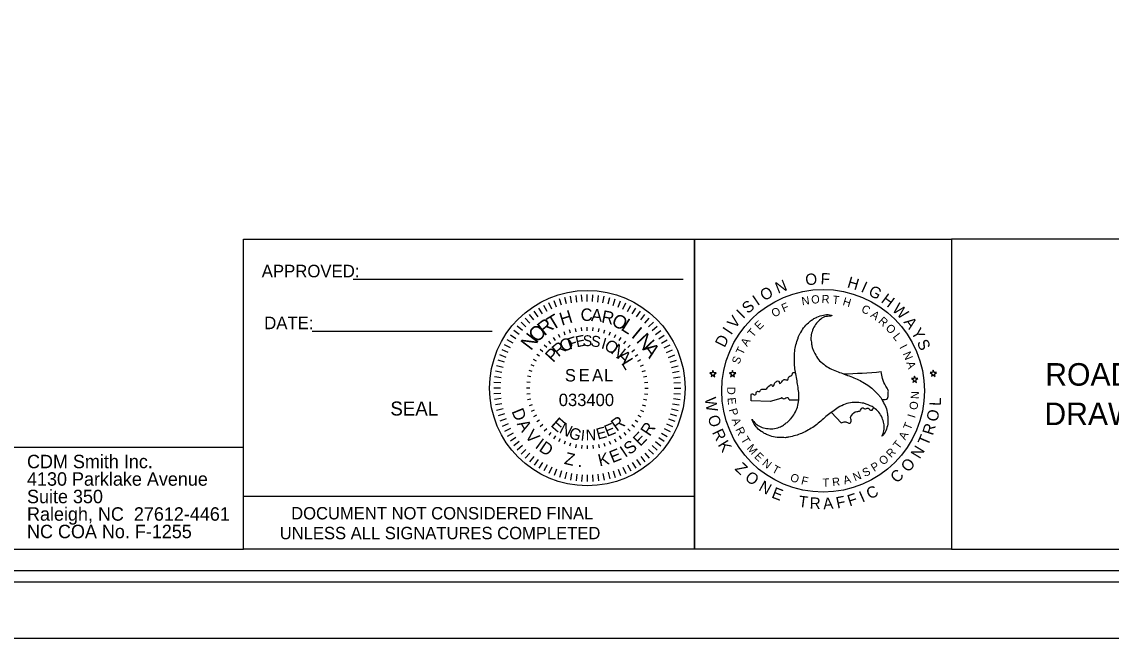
# Model space of a CAD drawing. Extents: x 0 to 1868, y 0 to 1100.
# Drawn here: x 1004.4 to 1487.6, y 0 to 273.5 of the extents above; entities that cross this region are included whole.
import ezdxf

# ---------------------------------------------------------------- set-up
doc = ezdxf.new("R2010")
doc.units = 0
for name, color, linetype in [('Exist Utilities Gas Test Hole SUE LOS A CELL', 7, 'Continuous'), ('Exist Utilities Sanitary Sewer Test Hole SUE LOS A CELL', 7, 'Continuous'), ('P_RDY_ROW_Permanent_Easement_CELL', 7, 'Continuous'), ('Sheet Block Title CELL', 7, 'Continuous'), ('Sheet_Cross_Section_Scale_CELL', 7, 'Continuous'), ('Sheet_Plan', 7, 'Continuous'), ('Sheet_Symbology_CELL', 7, 'Continuous')]:
    doc.layers.add(name, color=color, linetype=linetype)

msp = doc.modelspace()

# ---------------------------------------------------------------- linework, layer by layer
at = {"layer": 'Exist Utilities Gas Test Hole SUE LOS A CELL'}
for p, q in [((1309.58, 117.72), (1310.46, 117.07)), ((1310.66, 117.72), (1309.58, 117.72)), ((1310.46, 117.07), (1310.14, 116.03)), ((1310.14, 116.03), (1310.98, 116.67)), ((1310.98, 118.72), (1310.66, 117.72)), ((1311.34, 117.72), (1310.98, 118.72)), ((1310.98, 116.67), (1311.87, 116.03)), ((1310.98, 116.67), (1311.86, 116.03)), ((1312.43, 117.72), (1311.34, 117.72)), ((1311.54, 117.07), (1312.43, 117.72)), ((1311.54, 117.07), (1312.43, 117.72)), ((1311.87, 116.03), (1311.54, 117.07)), ((1311.86, 116.03), (1311.54, 117.07)), ((1319.34, 117.7), (1318.25, 117.7)), ((1318.25, 117.7), (1319.14, 117.06)), ((1319.14, 117.06), (1318.82, 116.02)), ((1318.82, 116.02), (1319.66, 116.66)), ((1319.66, 118.71), (1319.34, 117.7)), ((1320.02, 117.7), (1319.66, 118.71)), ((1319.66, 116.66), (1320.54, 116.02)), ((1321.1, 117.7), (1320.02, 117.7)), ((1320.22, 117.06), (1321.1, 117.7)), ((1320.54, 116.02), (1320.22, 117.06)), ((1400.43, 116.22), (1400.11, 115.21)), ((1400.79, 115.21), (1400.43, 116.22)), ((1408.38, 117.86), (1407.3, 117.86)), ((1407.3, 117.86), (1408.18, 117.21)), ((1408.18, 117.21), (1407.86, 116.17)), ((1407.86, 116.17), (1408.7, 116.81)), ((1408.7, 118.86), (1408.38, 117.86)), ((1409.07, 117.86), (1408.7, 118.86)), ((1408.7, 116.81), (1409.59, 116.17)), ((1410.15, 117.86), (1409.07, 117.86)), ((1409.27, 117.21), (1410.15, 117.86)), ((1409.59, 116.17), (1409.27, 117.21)), ((1400.11, 115.21), (1399.02, 115.21)), ((1399.02, 115.21), (1399.9, 114.57)), ((1399.9, 114.57), (1399.58, 113.53)), ((1399.58, 113.53), (1400.43, 114.17)), ((1400.43, 114.17), (1401.31, 113.53)), ((1401.87, 115.21), (1400.79, 115.21)), ((1400.99, 114.57), (1401.87, 115.21)), ((1401.31, 113.53), (1400.99, 114.57)), ((1327.9, 105.27), (1327.99, 107.93)), ((1341.1, 106.37), (1336.29, 104.96)), ((1336.29, 104.96), (1327.9, 105.27)), ((1344.8, 105.81), (1349.01, 105.77)), ((1363.55, 100.19), (1367.86, 95.52))]:
    msp.add_line(p, q, dxfattribs=at)
for start, end in [(265.6785, 265.9762), (271.2035, 275.3236)]:
    msp.add_arc((1363.94, 350.45), 233.19, start, end, dxfattribs=at)
for points in [[(1328.31, 97.16), (1330.06, 95.15), (1332.23, 93.75), (1334.73, 93.11), (1337.55, 92.94), (1340.42, 93.62), (1342.33, 94.58), (1343.13, 95.23), (1344.53, 96.33), (1345.52, 97.4), (1347.18, 99.76), (1348.47, 102.56), (1349.01, 105.75), (1349.04, 106.02), (1349.01, 109.02), (1348.61, 112.06), (1348.18, 114.98), (1347.64, 118.02), (1347.16, 121.02), (1347.1, 123.95), (1347.29, 127.31), (1347.78, 130.18), (1348.72, 133.13), (1349.23, 134.53), (1349.92, 135.66), (1351.67, 138.31), (1353.95, 140.46), (1355.45, 141.59), (1356.88, 142.34), (1357.12, 142.47), (1359.96, 143.38), (1362.75, 143.49), (1363.7, 143.25)], [(1363.77, 143.33), (1363.7, 143.25), (1361.12, 142.77), (1358.78, 141.56), (1356.98, 139.74), (1355.45, 137.4), (1354.6, 134.55), (1354.46, 132.43), (1354.65, 131.41), (1354.89, 129.64), (1355.29, 128.25), (1356.56, 125.64), (1358.3, 123.12), (1360.82, 121.05), (1361.04, 120.89), (1363.61, 119.41), (1366.49, 118.23), (1369.22, 117.16), (1372.1, 116.11), (1374.94, 114.98), (1377.52, 113.59), (1380.34, 111.76), (1382.56, 109.91), (1384.66, 107.63), (1385.63, 106.47), (1386.24, 105.3), (1387.69, 102.47), (1388.39, 99.41), (1388.63, 97.54), (1388.58, 95.92), (1388.58, 95.66), (1387.91, 92.73), (1386.59, 90.26), (1385.95, 89.59)], [(1327.99, 107.93), (1327.9, 108.18), (1328.35, 108.46), (1329.6, 107.95), (1330.22, 108.49), (1330.19, 109.03), (1330.7, 109.57), (1331.55, 109.4), (1332.31, 110.36), (1333.02, 110.56), (1334.51, 110.56), (1336.29, 112.33), (1337.03, 112.45), (1337.23, 111.97), (1337.68, 111.88), (1338.47, 113.35), (1338.67, 113.55), (1340.02, 114.11), (1340.39, 113.83), (1340.5, 113.18), (1340.7, 113.07), (1341.15, 113.38), (1341.78, 114.17), (1342.91, 114.77), (1344.21, 114.6), (1344.43, 115.67), (1345.96, 116.69), (1346.27, 117.31), (1346.35, 117.93)], [(1385.88, 106.04), (1388.34, 106.35), (1388.71, 108.3), (1388.74, 109.93), (1387.72, 111.83), (1386.2, 115.3), (1385.57, 118.27)], [(1344.8, 105.81), (1344.46, 106.46), (1343.78, 106.66), (1342.85, 106.18), (1342.17, 106.2), (1341.41, 106.77), (1341.1, 106.37)], [(1385.95, 89.59), (1386.81, 92.06), (1386.94, 94.66), (1386.24, 97.16), (1384.98, 99.65), (1382.97, 101.8), (1381.2, 102.98), (1380.2, 103.34), (1378.59, 104.03), (1377.12, 104.35), (1374.27, 104.59), (1371.18, 104.33), (1368.15, 103.17), (1367.91, 103.07), (1365.33, 101.54), (1362.89, 99.68), (1360.55, 97.86), (1358.22, 95.87), (1355.83, 93.94), (1353.33, 92.43), (1350.33, 90.9), (1347.61, 89.91), (1344.61, 89.24), (1343.1, 88.97), (1341.79, 89.03), (1338.65, 89.19), (1335.62, 90.1), (1333.9, 90.83), (1332.53, 91.71), (1332.29, 91.84), (1330.09, 93.86), (1328.61, 96.22), (1328.31, 97.16)], [(1367.86, 95.52), (1369.55, 96.03), (1370.96, 95.49), (1371.64, 95.38), (1372.21, 95.8), (1372.04, 97.93), (1372.52, 98.91), (1374.81, 100.61), (1376.22, 100.92), (1377.27, 102.22), (1377.69, 102.19), (1378.34, 101.82), (1379.78, 102.11), (1380.94, 101.17), (1381.62, 101.23), (1382.16, 102.29)]]:
    msp.add_spline(points, degree=3, dxfattribs=at)
at = {"layer": 'Exist Utilities Sanitary Sewer Test Hole SUE LOS A CELL'}
msp.add_lwpolyline([(0, 0), (1688, 0), (1688, 1100), (0, 1100)], close=True, dxfattribs=at)
at = {"layer": 'P_RDY_ROW_Permanent_Easement_CELL'}
for p, q in [((1151.36, 159.37), (1297.7, 159.37)), ((1302.85, 153.55), (1302.85, 39.55)), ((1133.24, 136.3), (1213.03, 136.3)), ((740.76, 30), (1652.71, 30)), ((173.28, 25), (1652.71, 25))]:
    msp.add_line(p, q, dxfattribs=at)
for points in [[(1102.81, 177.05), (1302.85, 177.05), (1302.85, 39.55), (1102.81, 39.55)], [(1302.85, 177.05), (1416.85, 177.05), (1416.85, 39.55), (1302.85, 39.55)], [(1652.85, 177.05), (1416.85, 177.05), (1416.85, 39.55), (1652.85, 39.55)]]:
    msp.add_lwpolyline(points, close=True, dxfattribs=at)
msp.add_circle((1255.25, 110.96), 43.34, dxfattribs=at)
at = {"layer": 'Sheet Block Title CELL'}
msp.add_lwpolyline([(907.1, 39.55), (1102.81, 39.55), (1102.81, 84.55), (907.1, 84.55)], close=True, dxfattribs=at)
at = {"layer": 'Sheet_Cross_Section_Scale_CELL'}
msp.add_circle((1359.85, 109.76), 44.97, dxfattribs=at)
at = {"layer": 'Sheet_Plan'}
for p, q in [((1243.8, 147.7), (1242.91, 150.56)), ((1246.04, 148.32), (1245.32, 151.23)), ((1248.31, 148.81), (1247.77, 151.76)), ((1250.61, 149.16), (1250.25, 152.13)), ((1252.92, 149.37), (1252.74, 152.36)), ((1255.25, 149.44), (1255.25, 152.44)), ((1257.57, 149.37), (1257.75, 152.36)), ((1259.89, 149.16), (1260.25, 152.13)), ((1262.18, 148.81), (1262.73, 151.76)), ((1264.46, 148.32), (1265.17, 151.23)), ((1266.69, 147.69), (1267.59, 150.56)), ((1233.39, 142.63), (1231.69, 145.09)), ((1235.34, 143.89), (1233.79, 146.46)), ((1237.37, 145.03), (1235.97, 147.68)), ((1239.46, 146.05), (1238.23, 148.78)), ((1241.6, 146.94), (1240.54, 149.74)), ((1268.89, 146.94), (1269.96, 149.74)), ((1271.04, 146.05), (1272.27, 148.78)), ((1273.13, 145.03), (1274.52, 147.68)), ((1275.15, 143.89), (1276.7, 146.46)), ((1277.1, 142.63), (1278.81, 145.09)), ((1228.04, 138.17), (1225.92, 140.29)), ((1229.73, 139.76), (1227.74, 142.01)), ((1231.52, 141.25), (1229.67, 143.61)), ((1278.98, 141.25), (1280.83, 143.61)), ((1280.76, 139.76), (1282.75, 142.01)), ((1282.46, 138.17), (1284.57, 140.29)), ((1224.96, 134.69), (1222.6, 136.54)), ((1226.45, 136.47), (1224.2, 138.46)), ((1245.5, 134.5), (1244.92, 135.89)), ((1247.85, 135.35), (1247.41, 136.78)), ((1250.28, 135.96), (1249.98, 137.43)), ((1252.75, 136.32), (1252.6, 137.81)), ((1255.25, 136.45), (1255.25, 137.94)), ((1257.75, 136.32), (1257.89, 137.81)), ((1260.22, 135.96), (1260.51, 137.43)), ((1262.64, 135.35), (1263.08, 136.78)), ((1265, 134.5), (1265.58, 135.89)), ((1284.05, 136.47), (1286.29, 138.46)), ((1285.54, 134.69), (1287.9, 136.54)), ((1222.32, 130.87), (1219.75, 132.42)), ((1223.58, 132.82), (1221.12, 134.52)), ((1239.08, 130.66), (1238.13, 131.82)), ((1241.09, 132.15), (1240.26, 133.4)), ((1243.23, 133.44), (1242.53, 134.76)), ((1267.26, 133.44), (1267.97, 134.76)), ((1269.41, 132.15), (1270.24, 133.4)), ((1271.42, 130.66), (1272.37, 131.82)), ((1286.92, 132.82), (1289.38, 134.52)), ((1288.18, 130.87), (1290.74, 132.42)), ((1219.27, 124.6), (1216.47, 125.67)), ((1220.16, 126.75), (1217.43, 127.98)), ((1221.18, 128.84), (1218.52, 130.23)), ((1234.06, 125.12), (1232.81, 125.95)), ((1235.55, 127.13), (1234.39, 128.08)), ((1237.23, 128.98), (1236.17, 130.04)), ((1273.27, 128.98), (1274.33, 130.04)), ((1274.95, 127.13), (1276.11, 128.08)), ((1276.44, 125.12), (1277.69, 125.95)), ((1289.32, 128.84), (1291.97, 130.24)), ((1290.34, 126.75), (1293.07, 127.98)), ((1291.22, 124.6), (1294.03, 125.67)), ((1217.89, 120.17), (1214.98, 120.89)), ((1218.51, 122.41), (1215.65, 123.3)), ((1231.7, 120.71), (1230.32, 121.28)), ((1232.77, 122.97), (1231.45, 123.68)), ((1277.72, 122.97), (1279.05, 123.68)), ((1278.79, 120.71), (1280.18, 121.28)), ((1291.99, 122.41), (1294.84, 123.3)), ((1292.61, 120.17), (1295.52, 120.89)), ((1217.4, 117.9), (1214.45, 118.44)), ((1230.25, 115.93), (1228.78, 116.22)), ((1230.86, 118.36), (1229.42, 118.79)), ((1279.63, 118.36), (1281.07, 118.79)), ((1280.24, 115.93), (1281.71, 116.22)), ((1293.1, 117.9), (1296.05, 118.44)), ((1216.84, 113.28), (1213.85, 113.46)), ((1217.05, 115.6), (1214.08, 115.96)), ((1229.89, 113.46), (1228.39, 113.61)), ((1280.61, 113.46), (1282.1, 113.61)), ((1293.44, 115.6), (1296.42, 115.96)), ((1293.66, 113.28), (1296.65, 113.46)), ((1216.77, 110.96), (1213.77, 110.96)), ((1216.84, 108.64), (1213.85, 108.46)), ((1217.05, 106.32), (1214.08, 105.96)), ((1229.76, 110.96), (1228.26, 110.96)), ((1229.89, 108.46), (1228.39, 108.32)), ((1280.61, 108.46), (1282.1, 108.32)), ((1280.73, 110.96), (1282.23, 110.96)), ((1293.44, 106.32), (1296.42, 105.96)), ((1293.66, 108.64), (1296.65, 108.46)), ((1293.73, 110.96), (1296.72, 110.96)), ((1217.4, 104.02), (1214.45, 103.48)), ((1217.89, 101.75), (1214.98, 101.03)), ((1230.25, 105.99), (1228.78, 105.7)), ((1230.86, 103.56), (1229.42, 103.13)), ((1279.63, 103.56), (1281.07, 103.13)), ((1280.24, 105.99), (1281.71, 105.7)), ((1292.61, 101.75), (1295.52, 101.03)), ((1293.1, 104.02), (1296.05, 103.48)), ((1218.51, 99.51), (1215.65, 98.62)), ((1219.27, 97.32), (1216.47, 96.25)), ((1231.7, 101.21), (1230.32, 100.63)), ((1232.77, 98.95), (1231.45, 98.24)), ((1234.06, 96.8), (1232.81, 95.97)), ((1276.44, 96.8), (1277.69, 95.97)), ((1277.72, 98.95), (1279.05, 98.24)), ((1278.79, 101.21), (1280.18, 100.63)), ((1291.22, 97.32), (1294.03, 96.25)), ((1291.99, 99.51), (1294.84, 98.62)), ((1220.16, 95.17), (1217.43, 93.94)), ((1221.18, 93.08), (1218.52, 91.69)), ((1235.55, 94.79), (1234.39, 93.84)), ((1237.23, 92.94), (1236.17, 91.88)), ((1273.27, 92.94), (1274.33, 91.88)), ((1274.95, 94.79), (1276.11, 93.84)), ((1289.32, 93.08), (1291.97, 91.69)), ((1290.34, 95.17), (1293.07, 93.94)), ((1222.32, 91.05), (1219.75, 89.5)), ((1223.58, 89.1), (1221.12, 87.4)), ((1224.96, 87.23), (1222.6, 85.38)), ((1239.08, 91.26), (1238.13, 90.1)), ((1241.09, 89.77), (1240.26, 88.52)), ((1243.23, 88.49), (1242.53, 87.16)), ((1245.5, 87.41), (1244.92, 86.03)), ((1265, 87.41), (1265.58, 86.03)), ((1267.26, 88.48), (1267.97, 87.16)), ((1269.41, 89.77), (1270.24, 88.52)), ((1271.42, 91.26), (1272.37, 90.1)), ((1285.54, 87.23), (1287.9, 85.38)), ((1286.92, 89.1), (1289.38, 87.4)), ((1288.18, 91.05), (1290.74, 89.5)), ((1226.45, 85.45), (1224.2, 83.46)), ((1228.04, 83.75), (1225.92, 81.63)), ((1229.73, 82.16), (1227.74, 79.92)), ((1247.85, 86.57), (1247.41, 85.14)), ((1250.28, 85.97), (1249.98, 84.49)), ((1252.75, 85.6), (1252.6, 84.11)), ((1255.25, 85.48), (1255.25, 83.98)), ((1257.75, 85.6), (1257.89, 84.11)), ((1260.22, 85.96), (1260.51, 84.49)), ((1262.64, 86.57), (1263.08, 85.14)), ((1280.76, 82.16), (1282.75, 79.92)), ((1282.46, 83.75), (1284.57, 81.63)), ((1284.05, 85.45), (1286.29, 83.46)), ((1231.52, 80.67), (1229.67, 78.31)), ((1233.39, 79.29), (1231.69, 76.83)), ((1235.34, 78.03), (1233.79, 75.47)), ((1275.15, 78.03), (1276.7, 75.47)), ((1277.1, 79.29), (1278.81, 76.83)), ((1278.98, 80.67), (1280.83, 78.31)), ((1237.37, 76.89), (1235.97, 74.23)), ((1239.46, 75.87), (1238.23, 73.14)), ((1241.61, 74.98), (1240.54, 72.18)), ((1243.8, 74.22), (1242.91, 71.36)), ((1246.04, 73.6), (1245.32, 70.69)), ((1248.31, 73.11), (1247.77, 70.16)), ((1250.61, 72.76), (1250.25, 69.79)), ((1252.92, 72.55), (1252.74, 69.56)), ((1257.57, 72.55), (1257.75, 69.56)), ((1259.89, 72.76), (1260.25, 69.79)), ((1262.18, 73.11), (1262.73, 70.16)), ((1264.46, 73.6), (1265.18, 70.69)), ((1266.69, 74.22), (1267.59, 71.36)), ((1268.89, 74.98), (1269.96, 72.18)), ((1271.04, 75.87), (1272.27, 73.14)), ((1273.13, 76.89), (1274.52, 74.23)), ((1255.25, 72.48), (1255.25, 69.48))]:
    msp.add_line(p, q, dxfattribs=at)
at = {"layer": 'Sheet_Symbology_CELL'}
for p, q in [((1102.81, 39.55), (1102.81, 63.05)), ((1102.81, 63.05), (1302.85, 63.05)), ((1302.85, 63.04), (1302.85, 39.54)), ((1302.85, 39.55), (1102.81, 39.55))]:
    msp.add_line(p, q, dxfattribs=at)

# ---------------------------------------------------------------- texts
at = {"layer": 'Exist Utilities Gas Test Hole SUE LOS A CELL'}
for s, height, rotation, p in [('O', 5.04, 5.7649, (1352.21, 156.5)), ('F', 5.04, 357.2575, (1358.66, 157.06)), ('H', 5.04, 343.454, (1370.23, 155.77)), ('O', 5.04, 30.0935, (1333.69, 149.44)), ('N', 5.04, 21.5861, (1339.82, 152.8)), ('I', 5.04, 335.804, (1376.28, 153.88)), ('G', 5.04, 331.5167, (1379.52, 152.49)), ('I', 5.04, 34.3808, (1330.72, 147.35)), ('N', 3.63, 9.0227, (1350.58, 147.69)), ('O', 3.63, 3.9446, (1354.69, 148.41)), ('R', 3.63, 358.8665, (1359.15, 148.7)), ('H', 3.63, 343.6322, (1368.27, 147.85)), ('H', 5.04, 323.4632, (1385.22, 149.28)), ('I', 5.04, 44.8722, (1324.4, 141.51)), ('S', 5.04, 40.5848, (1326.47, 143.71)), ('O', 3.63, 29.335, (1338.13, 142.2)), ('F', 3.63, 24.2569, (1342.35, 144.56)), ('C', 3.63, 333.4761, (1376.48, 144.95)), ('W', 5.04, 315.8133, (1390.14, 145.56)), ('V', 5.04, 51.5806, (1320.8, 137.03)), ('E', 3.63, 44.5692, (1331.55, 136.51)), ('A', 3.63, 323.3199, (1380.6, 142.83)), ('R', 3.63, 318.2418, (1384.08, 140.3)), ('A', 5.04, 306.7762, (1395.37, 140.24)), ('I', 5.04, 55.8679, (1319.03, 134.27)), ('T', 3.63, 49.6473, (1328.71, 133.22)), ('O', 3.63, 313.1637, (1387.3, 137.38)), ('L', 3.63, 308.0856, (1390.56, 133.66)), ('Y', 5.04, 299.7484, (1398.69, 135.8)), ('D', 5.04, 63.459, (1316.14, 128.66)), ('A', 3.63, 59.8035, (1326.13, 129.19)), ('S', 5.04, 293.2249, (1401.31, 131.3)), ('T', 3.63, 64.8816, (1324.22, 125.44)), ('I', 3.63, 297.9295, (1393.6, 129.17)), ('N', 3.63, 292.8514, (1395.12, 126.28)), ('S', 3.63, 69.9597, (1322.62, 121.27)), ('A', 3.63, 287.7733, (1396.71, 122.25)), ('D', 3.63, 270.272, (1317.29, 111.51)), ('E', 3.63, 275.3501, (1317.41, 106.65)), ('N', 3.63, 87.733, (1402.29, 106.05)), ('P', 3.63, 285.5063, (1318, 101.47)), ('O', 3.63, 82.9269, (1401.65, 101.15)), ('A', 3.63, 290.5843, (1319.19, 97.01)), ('I', 3.63, 72.7707, (1400.57, 97.44)), ('R', 3.63, 295.6624, (1320.85, 92.68)), ('T', 3.63, 67.6926, (1398.57, 92.06)), ('T', 3.63, 300.7405, (1323.16, 88.22)), ('T', 3.63, 52.4584, (1393.39, 83.58)), ('A', 3.63, 62.6145, (1396.32, 87.67)), ('M', 3.63, 310.8967, (1325.74, 84.16)), ('E', 3.63, 315.9748, (1329.09, 80.32)), ('R', 3.63, 47.3803, (1390.09, 79.79)), ('N', 3.63, 321.0529, (1332.51, 77.15)), ('P', 3.63, 32.146, (1382.48, 73.73)), ('O', 3.63, 42.3022, (1386.56, 76.54)), ('T', 3.63, 331.209, (1336.77, 73.9)), ('O', 3.63, 341.3652, (1344.92, 69.89)), ('N', 3.63, 21.9899, (1373.96, 69.57)), ('S', 3.63, 27.068, (1378.37, 71.44)), ('F', 3.63, 346.4433, (1349.86, 68.4)), ('T', 3.63, 1.6775, (1359.65, 67.19)), ('R', 3.63, 6.7556, (1364.08, 67.42)), ('A', 3.63, 16.9118, (1369.36, 68.18))]:
    msp.add_text(s, height=height, rotation=rotation, dxfattribs=at).set_placement(p)
at = {"layer": 'P_RDY_ROW_Permanent_Easement_CELL'}
for s, height, p in [('APPROVED:  ', 5.5567, (1110.83, 160.13)), ('DATE:  ', 5.557, (1111.92, 137.12)), ('ROADWAY STANDARD ', 10, (1458.39, 112.05)), ('SEAL', 6.203, (1167.88, 98.81)), ('DRAWINGS & LEGEND', 10, (1458, 94.55))]:
    msp.add_text(s, height=height, dxfattribs=at).set_placement(p)
at = {"layer": 'Sheet Block Title CELL'}
for s, height, p in [('CDM Smith Inc.', 5.9609, (1006.71, 75.42)), ('4130 Parklake Avenue', 5.9609, (1006.71, 67.66)), ('Suite 350', 5.961, (1006.71, 59.9)), ('Raleigh, NC  27612-4461', 5.9609, (1006.71, 52.14)), ('NC COA No. F-1255', 5.9609, (1006.71, 44.38))]:
    msp.add_text(s, height=height, rotation=359.9982, dxfattribs=at).set_placement(p)
at = {"layer": 'Sheet_Cross_Section_Scale_CELL'}
for s, height, rotation, p in [('T', 3.63, 353.7884, (1363.85, 148.47)), ('W', 5.04, 278.15, (1307.34, 106.56)), ('L', 5.04, 87.429, (1412.03, 102.99)), ('O', 5.04, 287.1147, (1308.56, 98.15)), ('O', 5.04, 78.9896, (1410.55, 95.82)), ('R', 5.04, 295.5541, (1310.51, 91.39)), ('R', 5.04, 72.7519, (1408.53, 89.72)), ('K', 5.04, 301.7918, (1312.98, 85.84)), ('T', 5.04, 66.881, (1406.29, 85.01)), ('N', 5.04, 58.892, (1402.69, 79.26)), ('Z', 5.04, 316.1688, (1320.41, 74.93)), ('O', 5.04, 50.4526, (1397.74, 73.29)), ('O', 5.04, 322.5233, (1324.77, 70.58)), ('C', 5.04, 43.0807, (1392.51, 68.51)), ('N', 5.04, 330.9626, (1330.92, 65.85)), ('E', 5.04, 338.9517, (1336.65, 62.5)), ('T', 5.04, 352.6948, (1348.69, 58.33)), ('F', 5.04, 11.7751, (1366.14, 57.51)), ('F', 5.04, 17.7627, (1371.56, 58.45)), ('I', 5.04, 23.7503, (1377.21, 60.11)), ('C', 5.04, 28.0033, (1380.65, 61.43)), ('R', 5.04, 358.5656, (1353.83, 57.46)), ('A', 5.04, 4.8034, (1360.03, 57.15))]:
    msp.add_text(s, height=height, rotation=rotation, dxfattribs=at).set_placement(p)
at = {"layer": 'Sheet_Plan'}
for s, height, rotation, p in [('H', 5.73, 17.1424, (1243.91, 138.63)), ('C', 5.5, 2.964, (1252.42, 140.64)), ('A', 5.51, 355.8747, (1256.78, 140.71)), ('R', 5.6, 348.7855, (1261.24, 140.13)), ('R', 6.3, 38.4101, (1236.19, 133.85)), ('T', 6.13, 31.3209, (1239.73, 136.38)), ('O', 5.96, 334.607, (1265.6, 139.01)), ('L', 6.16, 327.5178, (1269.76, 137.03)), ('N', 6.4, 52.5886, (1230.26, 127.3)), ('O', 6.4, 45.4993, (1232.94, 130.75)), ('I', 6.32, 320.4286, (1274.38, 133.79)), ('N', 6.41, 313.3394, (1276.65, 131.67)), ('R', 5.53, 40.0942, (1242.41, 124.52)), ('O', 5.39, 33.0621, (1245.05, 126.57)), ('F', 5.04, 18.9979, (1247.41, 127.98)), ('E', 4.9, 11.9657, (1250.57, 129.02)), ('S', 4.8, 357.9015, (1253.08, 129.69)), ('S', 4.86, 350.8694, (1256.5, 129.64)), ('I', 4.98, 343.8373, (1261.1, 128.67)), ('O', 5.32, 329.773, (1262.32, 128.42)), ('N', 5.48, 322.7409, (1265.35, 126.7)), ('P', 5.6, 47.1264, (1240.08, 122.02)), ('A', 5.58, 315.7088, (1267.95, 124.61)), ('A', 6.39, 306.2501, (1279.45, 128.33)), ('L', 5.51, 301.6445, (1270.15, 122.1)), ('S', 5.5, 0, (1245.3, 113.92)), ('E', 5.5, 0, (1251.4, 113.97)), ('A', 5.5, 0, (1257.36, 113.95)), ('L', 5.5, 0, (1262.68, 113.97)), ('033400', 5.497, 0, (1242.58, 103)), ('D', 5.4, 292.3254, (1221.56, 100.67)), ('E', 5.55, 318.5439, (1238.66, 94.3)), ('R', 5.45, 35.8972, (1268.27, 91.55)), ('A', 5.4, 300.5566, (1223.89, 95.09)), ('V', 5.4, 311.7772, (1227.32, 89.57)), ('N', 5.25, 332.6082, (1242.43, 91.38)), ('G', 5.07, 339.6403, (1246.62, 89.16)), ('I', 4.83, 353.7045, (1252.13, 87.72)), ('N', 4.8, 0.7366, (1254.55, 87.78)), ('E', 4.95, 14.8009, (1259.94, 88.08)), ('E', 5.11, 21.833, (1264.04, 89.31)), ('R', 5.4, 56.6621, (1282.95, 89.25)), ('I', 5.4, 323.2372, (1231.73, 84.75)), ('D', 5.4, 326.1338, (1233.45, 83.34)), ('S', 5.4, 36.7617, (1273.93, 81.14)), ('E', 5.4, 45.3772, (1278.75, 84.84)), ('Z', 5.4, 346.6654, (1244.71, 77.41)), ('K', 5.4, 13.3335, (1260.7, 76.21)), ('E', 5.4, 22.1784, (1266.38, 77.62)), ('I', 5.4, 33.8651, (1272.03, 79.98)), ('.', 5.4, 358.5162, (1250.95, 75.99))]:
    msp.add_text(s, height=height, rotation=rotation, dxfattribs=at).set_placement(p)
at = {"layer": 'Sheet_Symbology_CELL'}
for s, p in [('DOCUMENT NOT CONSIDERED FINAL', (1123.88, 52.71)), ('UNLESS ALL SIGNATURES COMPLETED', (1118.81, 43.91))]:
    msp.add_text(s, height=5.5, dxfattribs=at).set_placement(p)

doc.saveas('drawing.dxf')
